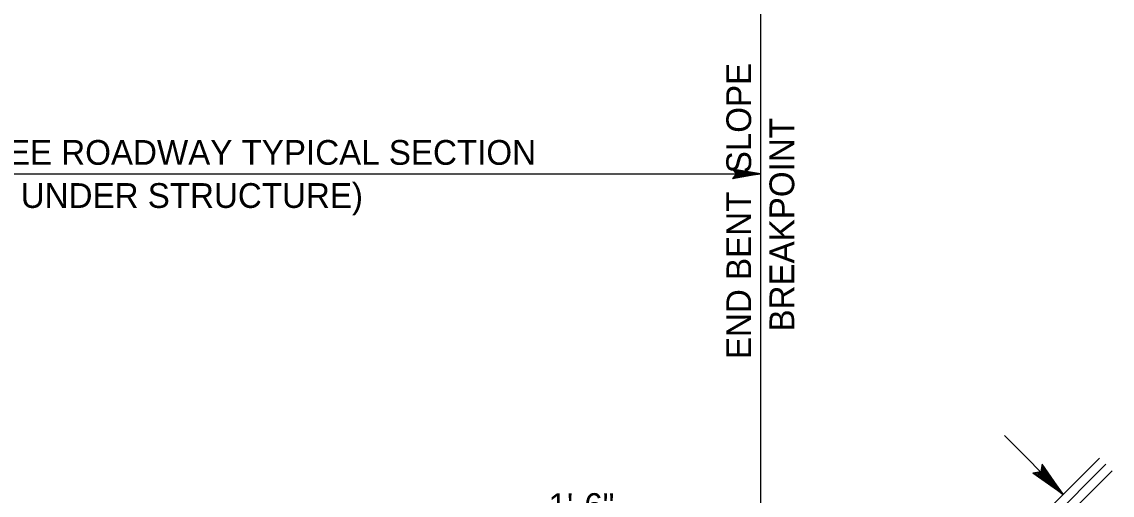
# Model space of a CAD drawing. Extents: x 1553195 to 1553792, y 810516 to 810787.
# Drawn here: x 1553751.08 to 1553774.19, y 810713.11 to 810723.14 of the extents above; entities that cross this region are included whole.
import ezdxf

# ---------------------------------------------------------------- set-up
doc = ezdxf.new("R2010")
doc.units = 0
doc.layers.add('Old_Level_28', color=7, linetype='Continuous')

msp = doc.modelspace()

# ---------------------------------------------------------------- linework, layer by layer
at = {"layer": 'Old_Level_28'}
for p, q in [((1553766.737, 810730.571), (1553766.737, 810707.494)), ((1553746.957, 810719.917), (1553766.737, 810719.917)), ((1553766.737, 810719.917), (1553766.143, 810720.019)), ((1553766.143, 810720.019), (1553766.22, 810719.917)), ((1553766.737, 810719.917), (1553766.143, 810719.81)), ((1553766.22, 810719.917), (1553766.143, 810719.81)), ((1553766.152, 810720.004), (1553766.737, 810719.917)), ((1553766.737, 810719.917), (1553766.152, 810719.826)), ((1553766.737, 810719.917), (1553766.164, 810719.99)), ((1553766.164, 810719.84), (1553766.737, 810719.917)), ((1553766.177, 810719.975), (1553766.737, 810719.917)), ((1553766.737, 810719.917), (1553766.177, 810719.855)), ((1553766.737, 810719.917), (1553766.185, 810719.96)), ((1553766.185, 810719.871), (1553766.737, 810719.917)), ((1553766.199, 810719.946), (1553766.737, 810719.917)), ((1553766.737, 810719.917), (1553766.199, 810719.884)), ((1553766.737, 810719.917), (1553766.21, 810719.931)), ((1553766.21, 810719.899), (1553766.737, 810719.917)), ((1553766.22, 810719.917), (1553766.737, 810719.917)), ((1553773.148, 810713.122), (1553771.904, 810714.368)), ((1553771.472, 810711.444), (1553773.92, 810713.892)), ((1553771.661, 810711.368), (1553774.055, 810713.761)), ((1553772.702, 810713.761), (1553772.677, 810713.597)), ((1553773.148, 810713.122), (1553772.688, 810713.668)), ((1553772.692, 810713.692), (1553773.148, 810713.122)), ((1553773.148, 810713.122), (1553772.695, 810713.715)), ((1553772.699, 810713.741), (1553773.148, 810713.122)), ((1553773.148, 810713.122), (1553772.702, 810713.761)), ((1553771.85, 810711.288), (1553774.188, 810713.623)), ((1553772.677, 810713.597), (1553772.508, 810713.57)), ((1553773.148, 810713.122), (1553772.508, 810713.57)), ((1553773.148, 810713.122), (1553772.533, 810713.572)), ((1553772.557, 810713.575), (1553773.148, 810713.122)), ((1553773.148, 810713.122), (1553772.581, 810713.584)), ((1553772.605, 810713.585), (1553773.148, 810713.122)), ((1553773.148, 810713.122), (1553772.628, 810713.588)), ((1553772.653, 810713.59), (1553773.148, 810713.122)), ((1553772.677, 810713.597), (1553773.148, 810713.122)), ((1553773.148, 810713.122), (1553772.679, 810713.621)), ((1553772.682, 810713.643), (1553773.148, 810713.122))]:
    msp.add_line(p, q, dxfattribs=at)

# ---------------------------------------------------------------- texts
for s, p in [('END BENT  SLOPE   ', (1553766.535, 810715.99)), ('   BREAKPOINT', (1553767.449, 810715.99))]:
    msp.add_text(s, height=0.52493, rotation=90, dxfattribs=at).set_placement(p)
for s, height, p in [('(SEE ROADWAY TYPICAL SECTION ', 0.52493, (1553750.08, 810720.109)), ('     UNDER STRUCTURE)', 0.52493, (1553750.08, 810719.195)), ('1\'-6"', 0.5249, (1553762.241, 810712.623))]:
    msp.add_text(s, height=height, dxfattribs=at).set_placement(p)

doc.saveas('drawing.dxf')
